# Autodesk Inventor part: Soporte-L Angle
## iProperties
Created: 2008-01
Part Number: Soporte-L Angle
Document SubType Name: Modeling
Designer: eruiz-tagle
Mass: 5.15903 g
Surface Area: 28.5172 cm^2
Volume: 5.15903 cm^3
Density: 1 g/cm^3
Author: eruiz-tagle
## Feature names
1. Extrusion1
2. Fillet1
3. Fillet2
